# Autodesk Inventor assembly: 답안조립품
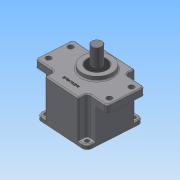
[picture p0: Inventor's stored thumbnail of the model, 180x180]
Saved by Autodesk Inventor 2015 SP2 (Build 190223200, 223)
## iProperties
Created: 2015-06
Part Number: 답안조립품
Document SubType Name: Assembly
Designer: AMC
Author: AMC
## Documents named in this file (12)
- C:\Users\AMC\Desktop\450620V1017\답안조립품.iam
- C:\Users\AMC\Desktop\450620V1017\1번본체.ipt
- C:\Users\AMC\Desktop\450620V1017\2번커버.ipt
- C:\Users\AMC\Desktop\450620V1017\베어링 608.ipt
- 베어링 608.ipt
- C:\Users\AMC\Desktop\450620V1017\메인축.ipt
- C:\Users\AMC\Desktop\450620V1017\서브축.ipt
- C:\Users\AMC\Desktop\450620V1017\베어링 6003.ipt
- 베어링 6003.ipt
- C:\Users\AMC\Desktop\450620V1017\오일실 8x22x7.ipt
- C:\Users\AMC\Desktop\450620V1017\오일실 17x32x8.ipt
- C:\Users\AMC\Desktop\450620V1017\M4x0.5x16.ipt
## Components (6 placed, 3 different names)
1. 1번본체:1
2. 2번커버:1
3. M4x0.5x12:1
4. M4x0.5x12:2
5. M4x0.5x12:3
6. M4x0.5x12:4
